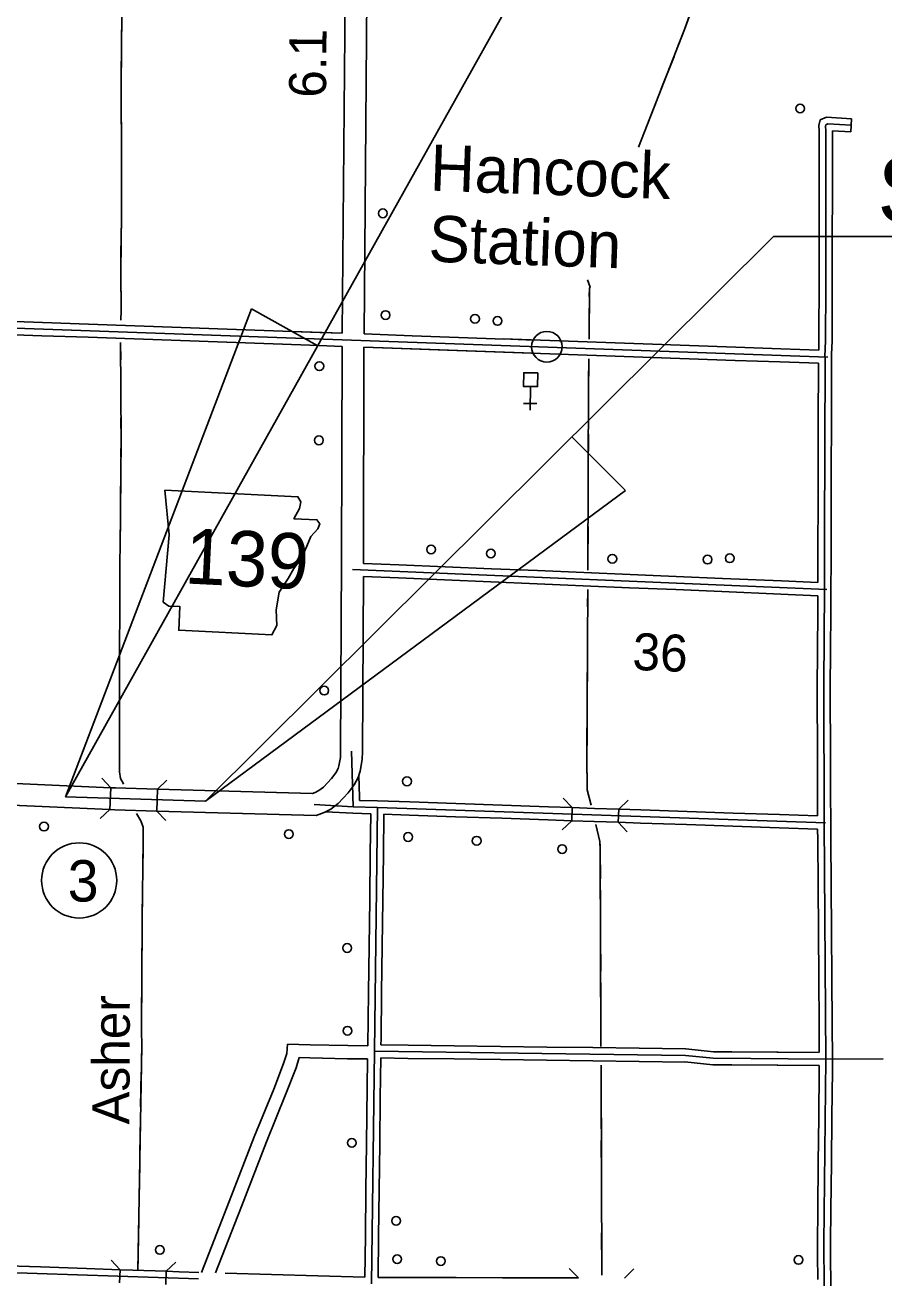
# Model space of a CAD drawing. Extents: x -4306 to 3843, y 131 to 8341.
# Drawn here: x 814 to 2383, y 4435 to 6723 of the extents above; entities that cross this region are included whole.
import ezdxf

# ---------------------------------------------------------------- set-up
doc = ezdxf.new("R2010")
doc.units = 0
for name, color, linetype in [('10', 7, 'Continuous'), ('21', 7, 'Continuous'), ('24', 7, 'Continuous'), ('32', 7, 'Continuous'), ('38', 7, 'Continuous'), ('46', 7, 'Continuous'), ('50', 7, 'Continuous'), ('52', 7, 'Continuous'), ('56', 7, 'Continuous'), ('57', 7, 'Continuous'), ('58', 7, 'Continuous'), ('61', 7, 'Continuous'), ('62', 7, 'Continuous')]:
    doc.layers.add(name, color=color, linetype=linetype)

msp = doc.modelspace()

# ---------------------------------------------------------------- linework, layer by layer
at = {"layer": '10'}
for p, q in [((1398.6, 6820.3), (1393.1, 6160.5)), ((1433.1, 6159.1), (1438.6, 6819.9)), ((1392.8, 6136.5), (1392.1, 5747.2)), ((1432, 5740.1), (1432.8, 6135.1)), ((1392.1, 5747.2), (1389.9, 5397.2)), ((1429.9, 5396.7), (1431.9, 5716.1)), ((1389.7, 5385.2), (1387.2, 5370.1)), ((1389.9, 5397.2), (1389.7, 5385.2)), ((1426.2, 5360.4), (1429.6, 5381.7)), ((1429.6, 5381.7), (1429.9, 5396.7)), ((1381.2, 5357.3), (1373.5, 5347)), ((1385.6, 5365.4), (1381.2, 5357.3)), ((1387.2, 5370.1), (1385.6, 5365.4)), ((1422.4, 5349.1), (1426.2, 5360.4)), ((1373.5, 5347), (1358.8, 5331.4)), ((1404.2, 5321.2), (1414.9, 5335.6)), ((1414.9, 5335.6), (1422.4, 5349.1)), ((970.3, 5330.2), (968.5, 5290.2)), ((970.2, 5330.2), (979.3, 5329.8)), ((979.3, 5329.8), (1055.4, 5327.7)), ((1055.5, 5327.7), (1054.4, 5287.7)), ((1338.9, 5319.9), (1055.4, 5327.7)), ((1344, 5321.7), (1338.9, 5319.9)), ((1350.7, 5325.3), (1344, 5321.7)), ((1358.8, 5331.4), (1350.7, 5325.3)), ((1385.6, 5301.5), (1404.2, 5321.2)), ((968.7, 5290.2), (977.9, 5289.8)), ((977.9, 5289.8), (1054.1, 5287.7)), ((1054.1, 5287.7), (1345.4, 5279.7)), ((1360.3, 5285.1), (1372.3, 5291.4)), ((1372.3, 5291.4), (1385.6, 5301.5)), ((1345.4, 5279.7), (1360.3, 5285.1))]:
    msp.add_line(p, q, dxfattribs=at)
for points in [[(581.8, 4463.7), (592.6, 5261.1), (598.4, 5277.4), (608.7, 5295.2), (624.9, 5312.8), (658.1, 5334.6), (688.3, 5342.8), (970.2, 5330.2)], [(968.7, 5290.2), (692.8, 5302.6), (674.8, 5297.7), (651, 5282.1), (641.1, 5271.4), (634.9, 5260.6), (632.5, 5254), (621.8, 4462.2)]]:
    msp.add_lwpolyline(points, dxfattribs=at)
at = {"layer": '21'}
msp.add_lwpolyline([(1069, 5873.9), (1077.2, 5792.2), (1065.8, 5669.4), (1076.3, 5662.1), (1096.6, 5661.2), (1094.5, 5617.9), (1264.8, 5609.6), (1273.8, 5626.7), (1272.5, 5655.3), (1278.1, 5687.5), (1294.2, 5712.5), (1304.6, 5730.9), (1319.1, 5750.6), (1328.3, 5771.8), (1335.9, 5789), (1348.8, 5803.3), (1352, 5812.6), (1346.9, 5819.7), (1305, 5821.7), (1315.4, 5840.2), (1317.3, 5852.3), (1312.2, 5861.9)], close=True, dxfattribs=at)
at = {"layer": '24'}
msp.add_circle((1766.9, 6135.8), 28, dxfattribs=at)
at = {"layer": '32'}
for p, q in [((2266.4, 6550.2), (2263.8, 6539.8)), ((2278, 6554.9), (2266.4, 6550.2)), ((2323.3, 6552.4), (2278, 6554.9)), ((2323.3, 6552.4), (2322, 6528.4)), ((2263.8, 6539.8), (2264.5, 6529.6)), ((2264.5, 6529.6), (2264.5, 6503.4)), ((2276.5, 6541.3), (2275.9, 6538.7)), ((2276.5, 6541.3), (2275.9, 6538.7)), ((2275.9, 6538.7), (2276.5, 6530)), ((2275.9, 6538.7), (2276.5, 6530)), ((2276.5, 6530), (2276.2, 6245.5)), ((2276.5, 6530), (2276.2, 6245.5)), ((2280, 6542.7), (2276.5, 6541.3)), ((2280, 6542.7), (2276.5, 6541.3)), ((2322.7, 6540.4), (2280, 6542.7)), ((2322.7, 6540.4), (2280, 6542.7)), ((2322, 6528.4), (2288.5, 6530.2)), ((2288.5, 6530.2), (2288.5, 6503.4)), ((2264.5, 6503.4), (2264.4, 6418.9)), ((2288.5, 6503.4), (2288.4, 6418.9)), ((2264.4, 6418.9), (2264.3, 6334.5)), ((2288.4, 6418.9), (2288.3, 6334.4)), ((2264.3, 6334.5), (2264.2, 6250)), ((2288.3, 6334.4), (2288.3, 6249.9)), ((2264.2, 6250), (2264.2, 6245.5)), ((2288.3, 6249.9), (2288.2, 6245.5)), ((2264.2, 6245.5), (2264, 6165.5)), ((2276.2, 6245.5), (2276, 6146.8)), ((2276.2, 6245.5), (2276, 6146.8)), ((2288.2, 6245.5), (2288, 6165.4)), ((845.4, 6180), (760.9, 6183)), ((929.8, 6177), (845.4, 6180)), ((2280.4, 6116.9), (569.1, 6177.8)), ((844.5, 6156), (760.1, 6159)), ((1014.2, 6174), (929.8, 6177)), ((1098.7, 6171), (1014.2, 6174)), ((1183.1, 6168), (1098.7, 6171)), ((1267.6, 6164.9), (1183.1, 6168)), ((1352, 6161.9), (1267.6, 6164.9)), ((1393.1, 6160.5), (1302, 6163.7)), ((1393.1, 6160.5), (1302, 6163.7)), ((1393.1, 6160.5), (1352, 6161.9)), ((1520.9, 6155.9), (1433.1, 6159.1)), ((2264, 6165.5), (2264, 6129.7)), ((2288, 6165.4), (2288, 6146.5)), ((929, 6153), (844.5, 6156)), ((1013.4, 6150), (929, 6153)), ((1097.8, 6147), (1013.4, 6150)), ((1182.3, 6144), (1097.8, 6147)), ((1266.7, 6141), (1182.3, 6144)), ((1351.1, 6138), (1266.7, 6141)), ((1392.8, 6136.5), (1351.1, 6138)), ((1741.5, 6124.1), (1432.8, 6135.1)), ((1857.8, 6119.9), (1432.8, 6135.1)), ((1520, 6132), (1432.8, 6135.1)), ((1605.3, 6152.9), (1520.9, 6155.9)), ((1689.7, 6149.9), (1605.3, 6152.9)), ((1943, 6140.9), (1687.3, 6150)), ((1741.7, 6148.1), (1687.3, 6150)), ((2027.5, 6137.9), (1943, 6140.9)), ((2111.9, 6134.9), (2027.5, 6137.9)), ((2194.1, 6132.2), (2111.9, 6134.9)), ((2276, 6146.8), (2274.8, 6117.7)), ((2276, 6146.8), (2274.8, 6117.7)), ((2288, 6146.5), (2287, 6121.8)), ((1604.4, 6128.9), (1520, 6132)), ((1688.9, 6125.9), (1604.4, 6128.9)), ((1942.2, 6116.9), (1857.8, 6119.9)), ((2026.6, 6113.9), (1942.2, 6116.9)), ((2111.1, 6110.9), (2026.6, 6113.9)), ((2192.5, 6108.2), (2111.1, 6110.9)), ((2264, 6129.7), (2194, 6132.2)), ((2275, 6114), (2274.1, 5793.5)), ((2275, 6114), (2274.1, 5793.5)), ((2274.8, 6117.7), (2275, 6114)), ((2274.8, 6117.7), (2275, 6114)), ((2287, 6121.8), (2286.9, 6081)), ((2262.9, 6105.7), (2192.6, 6108.3)), ((2262.9, 6105.7), (2262.7, 5996.6)), ((2286.9, 6081), (2286.7, 5996.5)), ((2262.7, 5996.6), (2262.4, 5912.1)), ((2286.7, 5996.5), (2286.4, 5912)), ((2262.4, 5912.1), (2262.2, 5827.6)), ((2286.4, 5912), (2286.2, 5827.5)), ((2262.2, 5827.6), (2262.1, 5793.5)), ((2286.2, 5827.5), (2286.1, 5793.5)), ((2262.1, 5793.5), (2262, 5743.1)), ((2274.1, 5793.5), (2273.8, 5693.1)), ((2274.1, 5793.5), (2273.8, 5693.1)), ((2286.1, 5793.5), (2286, 5743)), ((1411.9, 5728.9), (2278.2, 5692.6)), ((1432, 5740.1), (1496.8, 5737.4)), ((1496.8, 5737.4), (1581.2, 5733.8)), ((1581.2, 5733.8), (1665.6, 5730.3)), ((1665.6, 5730.3), (1750.1, 5726.8)), ((1750.1, 5726.8), (1834.5, 5723.2)), ((1834.5, 5723.2), (1918.9, 5719.7)), ((2262, 5743.1), (2261.9, 5705.1)), ((2286, 5743), (2285.8, 5693.1)), ((1431.9, 5716.1), (1495.8, 5713.4)), ((1495.8, 5713.4), (1580.2, 5709.9)), ((1580.2, 5709.9), (1664.6, 5706.3)), ((1664.6, 5706.3), (1749.1, 5702.8)), ((1749.1, 5702.8), (1833.5, 5699.2)), ((1833.5, 5699.2), (1917.9, 5695.7)), ((1918.9, 5719.7), (2003.3, 5716.1)), ((2003.3, 5716.1), (2087.7, 5712.6)), ((2087.7, 5712.6), (2195.4, 5707.9)), ((2261.9, 5705.1), (2195.4, 5707.9)), ((1917.9, 5695.7), (2002.3, 5692.2)), ((2002.3, 5692.2), (2086.7, 5688.6)), ((2086.7, 5688.6), (2194.4, 5683.9)), ((2261.8, 5681.1), (2194.4, 5683.9)), ((2261.8, 5681.1), (2261.6, 5658.6)), ((2273.8, 5693.1), (2272.6, 5518.6)), ((2273.8, 5693.1), (2272.6, 5518.6)), ((2285.8, 5693.1), (2285.6, 5658.5)), ((2261.6, 5658.6), (2261, 5574.2)), ((2285.6, 5658.5), (2285, 5574)), ((2261, 5574.2), (2260.6, 5518.6)), ((2285, 5574), (2284.6, 5518.6)), ((2260.6, 5518.6), (2260.7, 5489.6)), ((2272.6, 5518.6), (2273.4, 5266)), ((2272.6, 5518.6), (2273.4, 5266)), ((2284.6, 5518.6), (2284.7, 5489.6)), ((2260.7, 5489.6), (2261, 5405.1)), ((2284.7, 5489.6), (2285, 5405.1)), ((2261, 5405.1), (2261.2, 5320.6)), ((2285, 5405.1), (2285.2, 5320.7)), ((1409.9, 5396.9), (1412.9, 5295.6)), ((1423.2, 5352.9), (1424.4, 5312.8)), ((1424.4, 5312.8), (1424.6, 5307.2)), ((2261.2, 5320.6), (2261.4, 5278.7)), ((2285.2, 5320.7), (2285.4, 5266.1)), ((1412.9, 5295.6), (1342.1, 5299.8)), ((1457.4, 5294.3), (1412.9, 5295.6)), ((1457.8, 5306.3), (1424.6, 5307.2)), ((1457.4, 5294.3), (1451.8, 4848.8)), ((2275.9, 5266), (1457.4, 5294.3)), ((1516.4, 5304.2), (1457.8, 5306.2)), ((1600.8, 5301.3), (1516.4, 5304.2)), ((1685.3, 5298.4), (1600.8, 5301.3)), ((1769.7, 5295.5), (1685.3, 5298.4)), ((1813.2, 5294), (1769.7, 5295.5)), ((1813.2, 5294), (1812.3, 5270)), ((1854.1, 5292.6), (1813.2, 5294)), ((1898.1, 5291.1), (1854.1, 5292.6)), ((1898.1, 5291.1), (1897.3, 5267.1)), ((1938.6, 5289.7), (1898.1, 5291.1)), ((2023, 5286.7), (1938.6, 5289.7)), ((2107.4, 5283.8), (2023, 5286.7)), ((1412.4, 5283.6), (1362.9, 5286.5)), ((1445.3, 5282.6), (1412.4, 5283.6)), ((1445.3, 5282.6), (1444.4, 5209.9)), ((1469.3, 5281.8), (1468.4, 5209.6)), ((1515.5, 5280.2), (1469.3, 5281.8)), ((1600, 5277.3), (1515.5, 5280.2)), ((1684.4, 5274.4), (1600, 5277.3)), ((1768.9, 5271.5), (1684.4, 5274.4)), ((1812.3, 5270), (1768.9, 5271.5)), ((1853.3, 5268.6), (1812.3, 5270)), ((1897.3, 5267.1), (1853.3, 5268.6)), ((1937.7, 5265.7), (1897.3, 5267.1)), ((2022.2, 5262.8), (1937.7, 5265.7)), ((2191.8, 5281.1), (2107.4, 5283.8)), ((2191.8, 5281.1), (2261.4, 5278.7)), ((2273.4, 5266), (2276.7, 4834.6)), ((2273.4, 5266), (2276.7, 4834.6)), ((2285.4, 5266.1), (2285.6, 5236.2)), ((2106.6, 5259.8), (2022.2, 5262.8)), ((2191, 5257.2), (2106.6, 5259.8)), ((2191, 5257.2), (2261.5, 5254.7)), ((2261.5, 5254.7), (2261.6, 5236)), ((2261.6, 5236), (2262.3, 5151.5)), ((2285.6, 5236.2), (2286.3, 5151.7)), ((1444.4, 5209.9), (1443.3, 5125.4)), ((1468.4, 5209.6), (1467.3, 5125.1)), ((2262.3, 5151.5), (2262.9, 5067.1)), ((2286.3, 5151.7), (2286.9, 5067.2)), ((1443.3, 5125.4), (1442.2, 5041)), ((1467.3, 5125.1), (1466.2, 5040.7)), ((2262.9, 5067.1), (2263.6, 4982.6)), ((2286.9, 5067.2), (2287.6, 4982.8)), ((1442.2, 5041), (1441.1, 4956.5)), ((1466.2, 5040.7), (1465.1, 4956.2)), ((2263.6, 4982.6), (2264.2, 4898.1)), ((2287.6, 4982.8), (2288.2, 4898.3)), ((1441.1, 4956.5), (1439.9, 4858.8)), ((1465.1, 4956.2), (1464.1, 4871.7)), ((2264.2, 4898.1), (2264.6, 4846.6)), ((2288.2, 4898.3), (2288.7, 4834.6)), ((1464.1, 4871.7), (1463.9, 4860.6)), ((1463.9, 4860.6), (1513.3, 4859.9)), ((1513.3, 4859.9), (1597.8, 4858.8)), ((1597.8, 4858.8), (1682.3, 4857.7)), ((1682.3, 4857.7), (1766.8, 4856.6)), ((1766.8, 4856.6), (1851.2, 4855.5)), ((1851.2, 4855.5), (1935.7, 4854.4)), ((1935.7, 4854.4), (2020.2, 4853.2)), ((2020.2, 4853.2), (2020.5, 4853.2)), ((2020.5, 4853.2), (2071.6, 4848)), ((1439.6, 4834.8), (1437.6, 4679.9)), ((1451.8, 4848.8), (1446.4, 4423.8)), ((1451.8, 4848.8), (2020.4, 4841.2)), ((1463.6, 4836.6), (1462.7, 4764.1)), ((1463.6, 4836.6), (1513, 4835.9)), ((1513, 4835.9), (1597.5, 4834.8)), ((1597.5, 4834.8), (1682, 4833.7)), ((1682, 4833.7), (1766.4, 4832.6)), ((1766.4, 4832.6), (1850.9, 4831.5)), ((1850.9, 4831.5), (1935.4, 4830.4)), ((1935.4, 4830.4), (2019.9, 4829.2)), ((2019.1, 4829.3), (2070.2, 4824)), ((2019.9, 4829.2), (2020.2, 4829.2)), ((2020.4, 4841.2), (2070.9, 4836)), ((2070.9, 4836), (2276.7, 4834.5)), ((2071.6, 4848), (2104.7, 4847.8)), ((2104.7, 4847.8), (2189.2, 4847.2)), ((2263.1, 4846.9), (2187.1, 4847.4)), ((2276.7, 4834.6), (2273.1, 4498.1)), ((2276.7, 4834.6), (2273.1, 4498.1)), ((2276.7, 4834.6), (2381.1, 4835.3)), ((2288.7, 4834.6), (2288.5, 4813.6)), ((2070.2, 4824), (2104.5, 4823.8)), ((2104.5, 4823.8), (2189, 4823.2)), ((2264.6, 4822.8), (2187.3, 4823.4)), ((2264.5, 4813.8), (2263.6, 4729.3)), ((2264.6, 4822.6), (2264.5, 4813.8)), ((2288.5, 4813.6), (2287.6, 4729.1)), ((1462.7, 4764.1), (1461.6, 4679.6)), ((2263.6, 4729.3), (2262.7, 4644.9)), ((2287.6, 4729.1), (2286.7, 4644.6)), ((1437.6, 4679.9), (1436.5, 4595.5)), ((1461.6, 4679.6), (1460.5, 4595.2)), ((2262.7, 4644.9), (2261.8, 4560.4)), ((2286.7, 4644.6), (2285.8, 4560.1)), ((1436.5, 4595.5), (1435.5, 4511)), ((1460.5, 4595.2), (1459.5, 4510.7)), ((2261.8, 4560.4), (2261.1, 4498.1)), ((2285.8, 4560.1), (2285.1, 4498.1)), ((1435.5, 4511), (1434.5, 4436.2)), ((1459.5, 4510.7), (1458.5, 4435.8)), ((2261.1, 4498.1), (2261.3, 4475.7)), ((2273.1, 4498.1), (2273.7, 4420.5)), ((2273.1, 4498.1), (2273.7, 4420.5)), ((2285.1, 4498.1), (2285.3, 4475.8)), ((2261.3, 4475.7), (2261.6, 4432)), ((2285.3, 4475.8), (2285.7, 4420.3)), ((1130.8, 4433), (602.5, 4450.9)), ((841.8, 4454.8), (757.3, 4457.6)), ((926.2, 4451.9), (841.8, 4454.8)), ((987.3, 4449.9), (926.2, 4451.9)), ((987.3, 4449.9), (986.5, 4425.9)), ((1010.7, 4449.1), (987.3, 4449.9)), ((1071.7, 4447), (1010.7, 4449.1)), ((1071.8, 4447), (1071, 4423)), ((1095.1, 4446.2), (1071.8, 4447)), ((1131.2, 4445), (1095.1, 4446.2)), ((1263.9, 4441.1), (1179.5, 4443.6)), ((1348.4, 4438.7), (1263.9, 4441.1)), ((1434.5, 4436.2), (1348.4, 4438.7)), ((1517, 4435.6), (1458.5, 4435.8)), ((1601.5, 4435.4), (1517, 4435.6)), ((1686, 4435.2), (1601.5, 4435.4)), ((1770.5, 4434.9), (1686, 4435.2)), ((1824.7, 4434.8), (1770.5, 4434.9))]:
    msp.add_line(p, q, dxfattribs=at)
at = {"layer": '38'}
for points in [[(1796.8, 5311.5), (1813.2, 5294)], [(1898.1, 5291.1), (1915.6, 5307.5)], [(1812.3, 5270), (1794.8, 5253.6)], [(1913.7, 5249.5), (1897.3, 5267.1)], [(970.9, 4467.4), (987.3, 4449.9)], [(1071.8, 4447), (1089.3, 4463.4)], [(1807.7, 4451.8), (1824.7, 4434.8)], [(1908.7, 4434.6), (1925.7, 4451.5)]]:
    msp.add_lwpolyline(points, dxfattribs=at)
at = {"layer": '46'}
for p, q in [((1291.7, 4844.6), (1293.3, 4862)), ((1293.3, 4862), (1334.8, 4860.9)), ((1334.8, 4860.9), (1403.3, 4859.2)), ((1403.3, 4859.2), (1439.9, 4858.8)), ((1286.1, 4826.4), (1291.7, 4844.6)), ((1308.8, 4818.5), (1314.6, 4837.4)), ((1314.6, 4837.4), (1334.2, 4836.9)), ((1334.2, 4836.9), (1402.9, 4835.2)), ((1402.9, 4835.2), (1439.6, 4834.8)), ((1268, 4779.8), (1286.1, 4826.4)), ((1290.3, 4770.9), (1308.8, 4818.5)), ((1232.4, 4692.3), (1268, 4779.8)), ((1254.7, 4683.5), (1290.3, 4770.9)), ((1186.8, 4574.3), (1232.4, 4692.3)), ((1209.1, 4565.6), (1254.7, 4683.5)), ((1136.3, 4444.8), (1186.8, 4574.3)), ((1161.8, 4444.1), (1209.1, 4565.6))]:
    msp.add_line(p, q, dxfattribs=at)
at = {"layer": '50'}
for p, q in [((1913.7, 7148.4), (887.6, 5313.5)), ((2181.1, 6337.1), (1143.1, 5305.9)), ((3842.8, 6337.1), (2181.1, 6337.1)), ((887.6, 5313.5), (1227.7, 6204.9)), ((1227.7, 6204.9), (1348.4, 6137.4)), ((1910.3, 5873.2), (1812.8, 5971.3)), ((1143.1, 5305.9), (1910.3, 5873.2)), ((1143.1, 5305.9), (887.6, 5313.5))]:
    msp.add_line(p, q, dxfattribs=at)
msp.add_circle((912.7, 5160.9), 68.6, dxfattribs=at)
at = {"layer": '56'}
for points in [[(990.8, 6996.5), (990.7, 6986.2), (991, 6793.8), (990.1, 6688.9), (989.1, 6602.1), (990.1, 6491.2), (989.9, 6377.6), (988.5, 6273.2), (989.3, 6201.9), (988.9, 6184.6)], [(2018.5, 6715.3), (2052.2, 6811.3), (2055.6, 6821.5), (2055.7, 6833.3), (2055.3, 6856.5), (2057.5, 6941.1), (2058.4, 6963.3)], [(990.8, 6774.7), (990.3, 6711.4)], [(2018.5, 6715.3), (2029, 6745.2)], [(2018.5, 6715.3), (1934.1, 6500.6)], [(2018.5, 6715.3), (2006.9, 6685.8)], [(990.1, 6690.2), (990.1, 6688.9), (989.4, 6626.9)], [(1999.2, 6666.1), (1976, 6607.2)], [(989.1, 6605.7), (989.1, 6602.1), (989.6, 6542.4)], [(1968.3, 6587.5), (1945.1, 6528.5)], [(989.8, 6521.3), (990.1, 6491.2), (990.1, 6489.6)], [(990.1, 6489.6), (990, 6457.9)], [(990, 6436.8), (989.9, 6377.6), (989.8, 6373.4)], [(989.6, 6352.3), (988.7, 6288.9)], [(988.6, 6267.8), (989.3, 6204.4)], [(1841.2, 6258.1), (1845.8, 6244.8), (1844.7, 6243.1), (1843.9, 6149.8)], [(1841.2, 6258.1), (1845.8, 6244.8), (1844.7, 6243.1), (1844.5, 6227.5)], [(1844.4, 6206.3), (1843.9, 6149.8)], [(988.4, 6143.3), (989.1, 5966.3)], [(988.4, 6143.3), (988.5, 6111.6)], [(1843.6, 6113.5), (1843.2, 6070.2), (1841.7, 5727.9)], [(1843.6, 6113.5), (1843.3, 6081.8)], [(988.6, 6090.5), (988.9, 6027.1)], [(1843.2, 6060.7), (1842.9, 5997.3)], [(988.9, 6006), (989.1, 5966.3)], [(1842.8, 5976.2), (1842.5, 5912.8)], [(989.1, 5966.3), (987.4, 5768.6), (987.2, 5746.5)], [(989.1, 5966.3), (988.8, 5934.6)], [(988.6, 5913.5), (988.1, 5850.1)], [(1842.4, 5891.7), (1842.2, 5828.3)], [(987.9, 5829), (987.4, 5768.6), (987.3, 5765.7)], [(1842.1, 5807.2), (1841.8, 5743.8)], [(987.2, 5746.5), (986.2, 5491.9), (986.4, 5359.4), (988, 5347.3), (992.9, 5338.6), (993.9, 5336.8)], [(987.2, 5746.5), (987, 5714.8)], [(987, 5693.7), (986.7, 5630.4)], [(1841.6, 5692.4), (1840.2, 5389.5), (1840.4, 5326.3), (1847.8, 5298.2)], [(1841.6, 5692.4), (1841.4, 5660.8)], [(1841.3, 5639.6), (1841.1, 5576.3)], [(986.6, 5609.2), (986.4, 5545.9)], [(1841, 5555.2), (1840.7, 5491.8)], [(986.3, 5524.7), (986.2, 5491.9), (986.2, 5461.4)], [(1840.6, 5470.7), (1840.3, 5407.3)], [(986.2, 5440.3), (986.3, 5376.9)], [(1840.2, 5386.2), (1840.4, 5326.3), (1841.3, 5322.9)], [(1017.4, 5282.9), (1025.1, 5269.5), (1029.4, 5258.2), (1029.6, 5234.1), (1027.7, 5087.5), (1026.4, 4887), (1026.8, 4858.6), (1022.2, 4580.9), (1020.1, 4448.8)], [(1017.4, 5282.9), (1025.1, 5269.5), (1029.4, 5258.2), (1029.5, 5254)], [(1865.8, 4857.8), (1864.5, 5216.2), (1863.8, 5232), (1856.4, 5262.8)], [(1029.6, 5232.9), (1028.8, 5169.6)], [(1864.7, 5164), (1864.5, 5216.2), (1864, 5227.4)], [(1028.5, 5148.4), (1027.7, 5087.5), (1027.7, 5085.1)], [(1865, 5079.5), (1864.8, 5142.9)], [(1027.6, 5064), (1027.2, 5000.6)], [(1865.3, 4995.1), (1865.1, 5058.4)], [(1027, 4979.5), (1026.6, 4916.1)], [(1865.6, 4910.6), (1865.4, 4973.9)], [(1026.4, 4895), (1026.4, 4887), (1026.8, 4858.6), (1026.3, 4831.6)], [(1865.8, 4857.8), (1865.6, 4889.4)], [(1026, 4810.5), (1025.5, 4778.8)], [(1865.9, 4823.2), (1867.2, 4439.7)], [(1865.9, 4823.2), (1866, 4791.5)], [(1025.5, 4778.8), (1024.9, 4747.1)], [(1866.1, 4770.4), (1866.3, 4707)], [(1024.6, 4726), (1023.5, 4662.7)], [(1866.3, 4685.9), (1866.6, 4622.5)], [(1023.2, 4641.5), (1022.2, 4580.9), (1022.1, 4578.2)], [(1866.6, 4601.4), (1866.9, 4538.1)], [(1021.8, 4557.1), (1020.8, 4493.7)], [(1866.9, 4516.9), (1867.1, 4453.6)], [(1020.4, 4472.6), (1020.1, 4448.8)]]:
    msp.add_lwpolyline(points, dxfattribs=at)
at = {"layer": '57'}
for centre in [(2229.6, 6571), (1467.2, 6379.5), (1472.4, 6193.7), (1635.6, 6186.9), (1676.8, 6183), (1351.3, 6100.3), (1350.6, 5964.9), (1555.4, 5765.5), (1664.6, 5758.2), (1886.5, 5748.5), (2060.5, 5747), (2101, 5749.4), (1360.3, 5507.7), (1511.4, 5342), (848.4, 5259.3), (1295.6, 5245.6), (1513.4, 5240.3), (1638.7, 5233.4), (1794.8, 5218.2), (1402.1, 5037.5), (1402.9, 4886.4), (1410.7, 4681.5), (1491.5, 4539.1), (1060, 4486), (1493.5, 4469), (1573.2, 4465.6), (2226.5, 4467.7)]:
    msp.add_circle(centre, 8, dxfattribs=at)
at = {"layer": '58'}
for p, q in [((1736.3, 6020.2), (1737.1, 6063.2)), ((1748.5, 6031.9), (1724.5, 6032.4))]:
    msp.add_line(p, q, dxfattribs=at)
msp.add_lwpolyline([(1750.5, 6088), (1750.1, 6063), (1724.2, 6063.4), (1724.6, 6088.4)], close=True, dxfattribs=at)
at = {"layer": '62'}
for p, q in [((969.4, 5310.2), (969.4, 5310.2)), ((1054.9, 5307.7), (1054.9, 5307.7))]:
    msp.add_line(p, q, dxfattribs=at)
for points in [[(970.3, 5330.2), (954.1, 5347.9)], [(1072.9, 5344.2), (1055.5, 5327.7)], [(950.8, 5274), (968.5, 5290.2)], [(1054.4, 5287.7), (1070.9, 5270.2)]]:
    msp.add_lwpolyline(points, dxfattribs=at)

# ---------------------------------------------------------------- texts
at = {"layer": '21'}
msp.add_text('139', height=101.29, rotation=357.2006, dxfattribs=at).set_placement((1104, 5703.5))
at = {"layer": '24'}
for s, p in [('Hancock', (1552.5, 6421.1)), ('Station', (1549.9, 6291.5))]:
    msp.add_text(s, height=84.49, rotation=357.963, dxfattribs=at).set_placement(p)
at = {"layer": '50'}
for s, height, p in [('STA. 305+50.00', 121.064, (2370.8, 6362.1)), ('3', 75.7, (891.7, 5122.3))]:
    msp.add_text(s, height=height, dxfattribs=at).set_placement(p)
at = {"layer": '52'}
msp.add_text('36', height=67.59, rotation=357.6004, dxfattribs=at).set_placement((1922.4, 5545.7))
at = {"layer": '56'}
msp.add_text('Asher', height=67.59, rotation=89.7677, dxfattribs=at).set_placement((1004.3, 4715))
at = {"layer": '61'}
msp.add_text('6.1', height=67.59, rotation=89.5179, dxfattribs=at).set_placement((1363.5, 6590.5))

doc.saveas('drawing.dxf')
